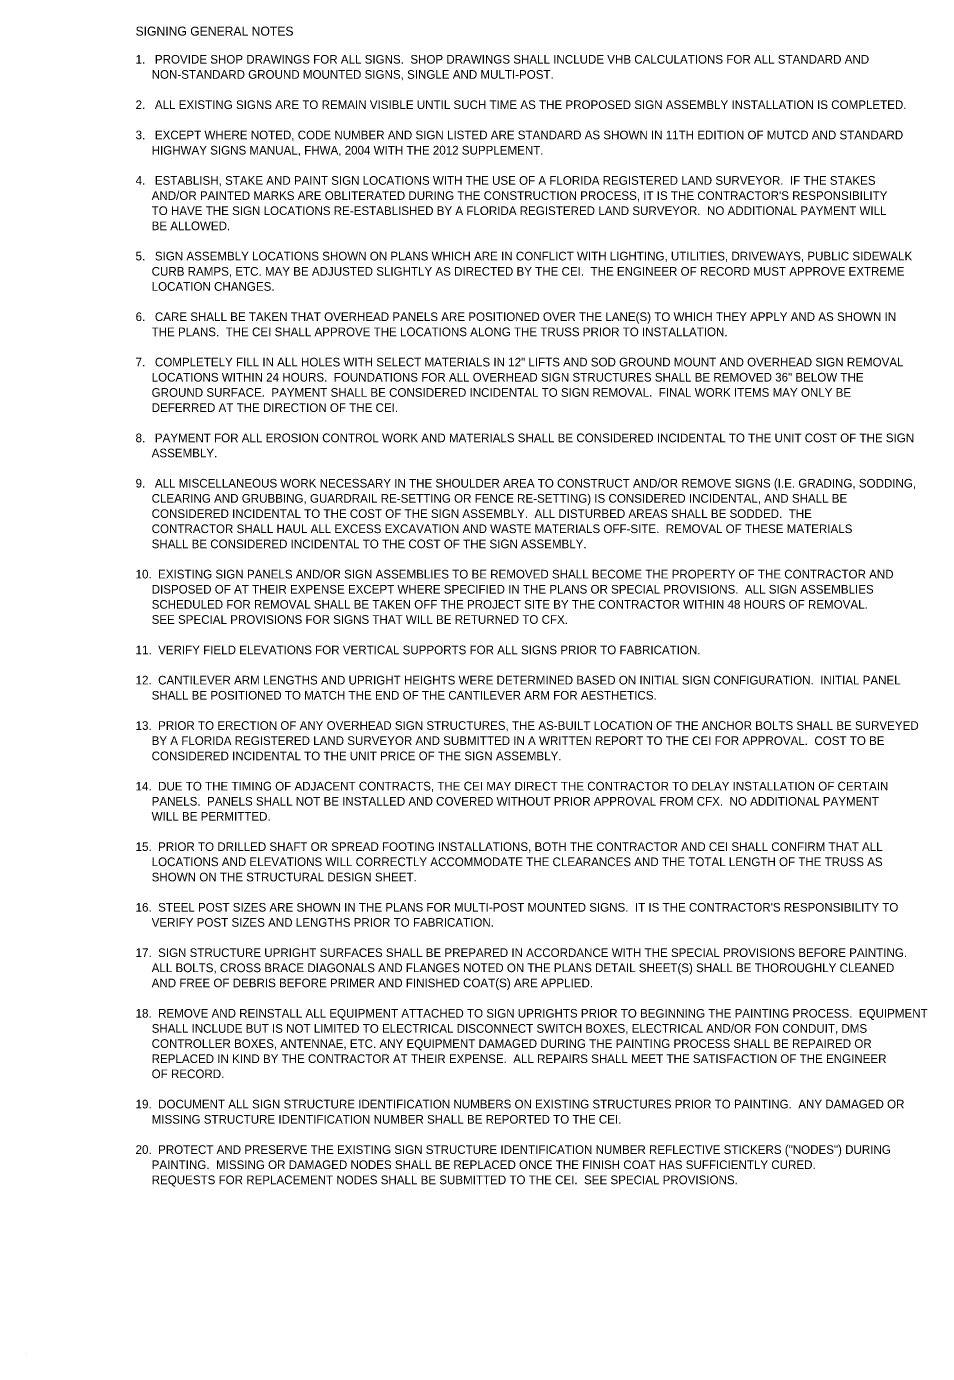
# Model space of a CAD drawing. Extents: x 2479946 to 2481516, y 3680184 to 3681234.
# Drawn here: x 2479946 to 2480648, y 3680184 to 3681219 of the extents above; entities that cross this region are included whole.
import ezdxf

# ---------------------------------------------------------------- set-up
doc = ezdxf.new("R2010")
doc.units = 0
doc.layers.add('AdhocPoint_dp', color=7, linetype='Continuous')
doc.layers.add('TextLabel', color=7, linetype='Continuous')

msp = doc.modelspace()

# ---------------------------------------------------------------- linework, layer by layer
at = {"layer": 'AdhocPoint_dp'}
msp.add_line((2479945.9, 3680184.2), (2479945.9, 3680184.2), dxfattribs=at)

# ---------------------------------------------------------------- texts
at = {"layer": 'TextLabel'}
for s, height, p in [('SIGNING GENERAL NOTES', 7.08, (2480030.9, 3681212.2)), ('1.   PROVIDE SHOP DRAWINGS FOR ALL SIGNS.  SHOP DRAWINGS SHALL INCLUDE VHB CALCULATIONS FOR ALL STANDARD AND', 6.75, (2480030.9, 3681190.4)), ('     NON-STANDARD GROUND MOUNTED SIGNS, SINGLE AND MULTI-POST.', 6.75, (2480030.9, 3681178.6)), ('2.   ALL EXISTING SIGNS ARE TO REMAIN VISIBLE UNTIL SUCH TIME AS THE PROPOSED SIGN ASSEMBLY INSTALLATION IS COMPLETED.', 6.75, (2480030.9, 3681155)), ('3.   EXCEPT WHERE NOTED, CODE NUMBER AND SIGN LISTED ARE STANDARD AS SHOWN IN 11TH EDITION OF MUTCD AND STANDARD ', 6.75, (2480030.9, 3681131.4)), ('     HIGHWAY SIGNS MANUAL, FHWA, 2004 WITH THE 2012 SUPPLEMENT.', 6.75, (2480030.9, 3681119.5)), ('4.   ESTABLISH, STAKE AND PAINT SIGN LOCATIONS WITH THE USE OF A FLORIDA REGISTERED LAND SURVEYOR.  IF THE STAKES', 6.75, (2480030.9, 3681095.9)), ("     AND/OR PAINTED MARKS ARE OBLITERATED DURING THE CONSTRUCTION PROCESS, IT IS THE CONTRACTOR'S RESPONSIBILITY", 6.75, (2480030.9, 3681084.1)), ('     TO HAVE THE SIGN LOCATIONS RE-ESTABLISHED BY A FLORIDA REGISTERED LAND SURVEYOR.  NO ADDITIONAL PAYMENT WILL', 6.75, (2480030.9, 3681072.3)), ('     BE ALLOWED.', 6.75, (2480030.9, 3681060.5)), ('5.   SIGN ASSEMBLY LOCATIONS SHOWN ON PLANS WHICH ARE IN CONFLICT WITH LIGHTING, UTILITIES, DRIVEWAYS, PUBLIC SIDEWALK', 6.75, (2480030.9, 3681036.9)), ('     CURB RAMPS, ETC. MAY BE ADJUSTED SLIGHTLY AS DIRECTED BY THE CEI.  THE ENGINEER OF RECORD MUST APPROVE EXTREME', 6.75, (2480030.9, 3681025)), ('     LOCATION CHANGES. ', 6.75, (2480030.9, 3681013.2)), ('6.   CARE SHALL BE TAKEN THAT OVERHEAD PANELS ARE POSITIONED OVER THE LANE(S) TO WHICH THEY APPLY AND AS SHOWN IN', 6.75, (2480030.9, 3680989.6)), ('     THE PLANS.  THE CEI SHALL APPROVE THE LOCATIONS ALONG THE TRUSS PRIOR TO INSTALLATION.', 6.75, (2480030.9, 3680977.8)), ('7.   COMPLETELY FILL IN ALL HOLES WITH SELECT MATERIALS IN 12" LIFTS AND SOD GROUND MOUNT AND OVERHEAD SIGN REMOVAL', 6.75, (2480030.9, 3680954.2)), ('     LOCATIONS WITHIN 24 HOURS.  FOUNDATIONS FOR ALL OVERHEAD SIGN STRUCTURES SHALL BE REMOVED 36" BELOW THE', 6.75, (2480030.9, 3680942.4)), ('     GROUND SURFACE.  PAYMENT SHALL BE CONSIDERED INCIDENTAL TO SIGN REMOVAL.  FINAL WORK ITEMS MAY ONLY BE', 6.75, (2480030.9, 3680930.5)), ('     DEFERRED AT THE DIRECTION OF THE CEI.', 6.75, (2480030.9, 3680918.7)), ('8.   PAYMENT FOR ALL EROSION CONTROL WORK AND MATERIALS SHALL BE CONSIDERED INCIDENTAL TO THE UNIT COST OF THE SIGN', 6.75, (2480030.9, 3680895.1)), ('     ASSEMBLY.', 6.75, (2480030.9, 3680883.3)), ('9.   ALL MISCELLANEOUS WORK NECESSARY IN THE SHOULDER AREA TO CONSTRUCT AND/OR REMOVE SIGNS (I.E. GRADING, SODDING,', 6.75, (2480030.9, 3680859.7)), ('     CLEARING AND GRUBBING, GUARDRAIL RE-SETTING OR FENCE RE-SETTING) IS CONSIDERED INCIDENTAL, AND SHALL BE', 6.75, (2480030.9, 3680847.9)), ('     CONSIDERED INCIDENTAL TO THE COST OF THE SIGN ASSEMBLY.  ALL DISTURBED AREAS SHALL BE SODDED.  THE  ', 6.75, (2480030.9, 3680836)), ('     CONTRACTOR SHALL HAUL ALL EXCESS EXCAVATION AND WASTE MATERIALS OFF-SITE.  REMOVAL OF THESE MATERIALS  ', 6.75, (2480030.9, 3680824.2)), ('     SHALL BE CONSIDERED INCIDENTAL TO THE COST OF THE SIGN ASSEMBLY.', 6.75, (2480030.9, 3680812.4)), ('10.  EXISTING SIGN PANELS AND/OR SIGN ASSEMBLIES TO BE REMOVED SHALL BECOME THE PROPERTY OF THE CONTRACTOR AND', 6.75, (2480030.9, 3680788.8)), ('     DISPOSED OF AT THEIR EXPENSE EXCEPT WHERE SPECIFIED IN THE PLANS OR SPECIAL PROVISIONS.  ALL SIGN ASSEMBLIES', 6.75, (2480030.9, 3680777)), ('     SCHEDULED FOR REMOVAL SHALL BE TAKEN OFF THE PROJECT SITE BY THE CONTRACTOR WITHIN 48 HOURS OF REMOVAL.', 6.75, (2480030.9, 3680765.2)), ('     SEE SPECIAL PROVISIONS FOR SIGNS THAT WILL BE RETURNED TO CFX.', 6.75, (2480030.9, 3680753.4)), ('11.  VERIFY FIELD ELEVATIONS FOR VERTICAL SUPPORTS FOR ALL SIGNS PRIOR TO FABRICATION.', 6.75, (2480030.9, 3680729.7)), ('12.  CANTILEVER ARM LENGTHS AND UPRIGHT HEIGHTS WERE DETERMINED BASED ON INITIAL SIGN CONFIGURATION.  INITIAL PANEL', 6.75, (2480030.9, 3680706.1)), ('     SHALL BE POSITIONED TO MATCH THE END OF THE CANTILEVER ARM FOR AESTHETICS.', 6.75, (2480030.9, 3680694.3)), ('13.  PRIOR TO ERECTION OF ANY OVERHEAD SIGN STRUCTURES, THE AS-BUILT LOCATION OF THE ANCHOR BOLTS SHALL BE SURVEYED', 6.75, (2480030.9, 3680670.7)), ('     BY A FLORIDA REGISTERED LAND SURVEYOR AND SUBMITTED IN A WRITTEN REPORT TO THE CEI FOR APPROVAL.  COST TO BE', 6.75, (2480030.9, 3680658.9)), ('     CONSIDERED INCIDENTAL TO THE UNIT PRICE OF THE SIGN ASSEMBLY.', 6.75, (2480030.9, 3680647)), ('14.  DUE TO THE TIMING OF ADJACENT CONTRACTS, THE CEI MAY DIRECT THE CONTRACTOR TO DELAY INSTALLATION OF CERTAIN', 6.75, (2480030.9, 3680623.4)), ('     PANELS.  PANELS SHALL NOT BE INSTALLED AND COVERED WITHOUT PRIOR APPROVAL FROM CFX.  NO ADDITIONAL PAYMENT', 6.75, (2480030.9, 3680611.6)), ('     WILL BE PERMITTED.', 6.75, (2480030.9, 3680599.8)), ('15.  PRIOR TO DRILLED SHAFT OR SPREAD FOOTING INSTALLATIONS, BOTH THE CONTRACTOR AND CEI SHALL CONFIRM THAT ALL', 6.75, (2480030.9, 3680576.2)), ('     LOCATIONS AND ELEVATIONS WILL CORRECTLY ACCOMMODATE THE CLEARANCES AND THE TOTAL LENGTH OF THE TRUSS AS', 6.75, (2480030.9, 3680564.4)), ('     SHOWN ON THE STRUCTURAL DESIGN SHEET.', 6.75, (2480030.9, 3680552.5)), ("16.  STEEL POST SIZES ARE SHOWN IN THE PLANS FOR MULTI-POST MOUNTED SIGNS.  IT IS THE CONTRACTOR'S RESPONSIBILITY TO", 6.75, (2480030.9, 3680528.9)), ('     VERIFY POST SIZES AND LENGTHS PRIOR TO FABRICATION.', 6.75, (2480030.9, 3680517.1)), ('17.  SIGN STRUCTURE UPRIGHT SURFACES SHALL BE PREPARED IN ACCORDANCE WITH THE SPECIAL PROVISIONS BEFORE PAINTING.', 6.75, (2480030.9, 3680493.5)), ('     ALL BOLTS, CROSS BRACE DIAGONALS AND FLANGES NOTED ON THE PLANS DETAIL SHEET(S) SHALL BE THOROUGHLY CLEANED', 6.75, (2480030.9, 3680481.7)), ('     AND FREE OF DEBRIS BEFORE PRIMER AND FINISHED COAT(S) ARE APPLIED.', 6.75, (2480030.9, 3680469.9)), ('18.  REMOVE AND REINSTALL ALL EQUIPMENT ATTACHED TO SIGN UPRIGHTS PRIOR TO BEGINNING THE PAINTING PROCESS.  EQUIPMENT', 6.75, (2480030.9, 3680446.2)), ('     SHALL INCLUDE BUT IS NOT LIMITED TO ELECTRICAL DISCONNECT SWITCH BOXES, ELECTRICAL AND/OR FON CONDUIT, DMS', 6.75, (2480030.9, 3680434.4)), ('     CONTROLLER BOXES, ANTENNAE, ETC. ANY EQUIPMENT DAMAGED DURING THE PAINTING PROCESS SHALL BE REPAIRED OR', 6.75, (2480030.9, 3680422.6)), ('     REPLACED IN KIND BY THE CONTRACTOR AT THEIR EXPENSE.  ALL REPAIRS SHALL MEET THE SATISFACTION OF THE ENGINEER', 6.75, (2480030.9, 3680410.8)), ('     OF RECORD.', 6.75, (2480030.9, 3680399)), ('19.  DOCUMENT ALL SIGN STRUCTURE IDENTIFICATION NUMBERS ON EXISTING STRUCTURES PRIOR TO PAINTING.  ANY DAMAGED OR', 6.75, (2480030.9, 3680375.4)), ('     MISSING STRUCTURE IDENTIFICATION NUMBER SHALL BE REPORTED TO THE CEI.', 6.75, (2480030.9, 3680363.5)), ('20.  PROTECT AND PRESERVE THE EXISTING SIGN STRUCTURE IDENTIFICATION NUMBER REFLECTIVE STICKERS ("NODES") DURING', 6.75, (2480030.9, 3680339.9)), ('     PAINTING.  MISSING OR DAMAGED NODES SHALL BE REPLACED ONCE THE FINISH COAT HAS SUFFICIENTLY CURED.', 6.75, (2480030.9, 3680328.1)), ('     REQUESTS FOR REPLACEMENT NODES SHALL BE SUBMITTED TO THE CEI.  SEE SPECIAL PROVISIONS.', 6.75, (2480030.9, 3680316.3))]:
    msp.add_text(s, height=height, dxfattribs=at).set_placement(p)

doc.saveas('drawing.dxf')
